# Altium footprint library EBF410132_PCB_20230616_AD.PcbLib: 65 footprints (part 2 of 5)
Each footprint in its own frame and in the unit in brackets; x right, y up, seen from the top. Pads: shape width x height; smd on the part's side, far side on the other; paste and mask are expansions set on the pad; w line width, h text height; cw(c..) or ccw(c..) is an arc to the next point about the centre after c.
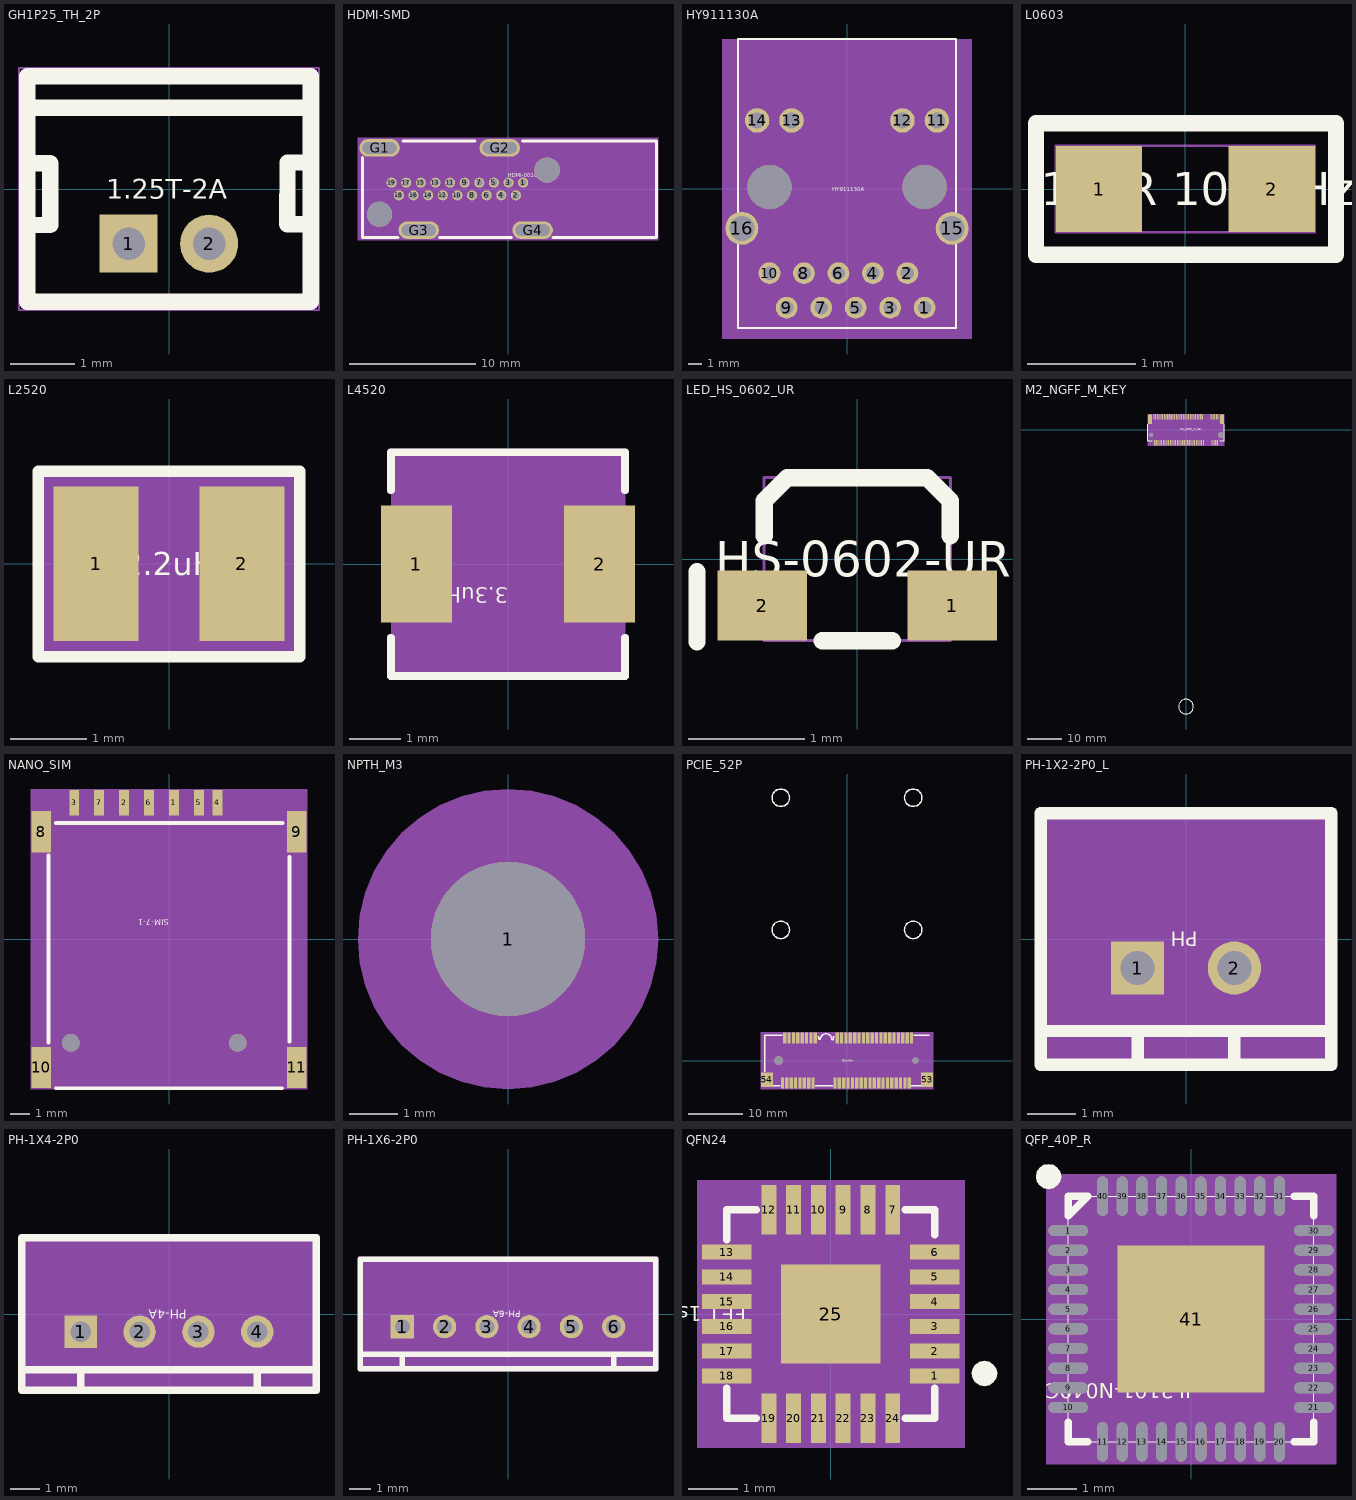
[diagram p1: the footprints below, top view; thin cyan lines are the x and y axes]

## GH1P25_TH_2P [mm] "GH1P25_TH_2P"
pads (2):
  rect 0.9x0.9 hole 0.5: 1(-0.626,-0.849)
  round 0.9 hole 0.5: 2(0.624,-0.849)
Top Overlay:
  lines w0.254: -2.202,0.401 -1.841,0.401 -1.841,-0.559 -2.161,-0.559 ; -2.201,1.262 2.199,1.262 ; 2.159,-0.549 1.839,-0.548 1.839,0.411 2.2,0.411 ; 2.199,-1.749 -2.201,-1.749 -2.201,1.751 2.199,1.751 ; 2.202,-1.751 2.202,1.749
  text "1.25T-2A" at -0.975,-0.152 h0.3
Top 3D Body:
  lines w0.025: -2.329,-1.878 2.329,-1.878 2.329,1.878 -2.329,1.878 -2.329,-1.878
Mechanical 15:
  text "2" at 0.37,-0.849 h0.64
  text "1" at -0.88,-0.849 h0.64

## HDMI-SMD [mm] "HDMI-SMD"
pads (25):
  round 0.8 hole 0.55: 1(1.194,0.5) 2(0.626,-0.5) 3(0.039,0.5) 4(-0.531,-0.5) 5(-1.116,0.5) 6(-1.687,-0.5) 7(-2.271,0.5) 8(-2.843,-0.5) 9(-3.425,0.5) 10(-3.998,-0.5) 11(-4.581,0.5) 12(-5.154,-0.5) 13(-5.736,0.5) 14(-6.31,-0.5) 15(-6.891,0.5) 16(-7.467,-0.5) 17(-8.045,0.5) 18(-8.623,-0.5) 19(-9.2,0.5)
  oval 3.2x1.4 hole 2.7 slot 0.9 at 90 deg: G1(-10.156,3.25) G2(-0.656,3.25) G3(-7.056,-3.25) G4(1.945,-3.25)
  round 2 hole 2 unplated: ""(-10.156,-2) ""(3.094,1.5)
Top Overlay:
  lines w0.254: -11.511,2.466 -11.511,-3.833 -8.699,-3.833 -8.696,-3.83 ; -8.295,3.786 -2.617,3.786 ; -5.422,-3.834 0.277,-3.834 ; 1.151,3.786 11.73,3.786 11.73,-3.834 3.588,-3.834 3.584,-3.83
  text "HDMI-001C" at 0,0.945 h0.3
Top 3D Body:
  region: -11.857,-4.052 11.857,-4.052 11.857,4.052 -11.857,4.052
Mechanical 15:
  text "2" at 0.626,-0.246 h0.64
  text "8" at -2.843,-0.246 h0.64
  text "5" at -1.116,0.754 h0.64
  text "11" at -4.581,1.008 h0.64
  text "17" at -8.045,1.008 h0.64
  text "13" at -5.736,1.008 h0.64
  text "18" at -8.623,0.008 h0.64
  text "19" at -9.2,1.008 h0.64
  text "G2" at -0.656,3.758 h0.64
  text "G4" at 1.945,-2.742 h0.64
  text "G1" at -10.156,3.758 h0.64
  text "G3" at -7.056,-2.742 h0.64
  text "15" at -6.891,1.008 h0.64
  text "16" at -7.467,0.008 h0.64
  text "12" at -5.154,0.008 h0.64
  text "10" at -3.998,0.008 h0.64
  text "9" at -3.425,0.754 h0.64
  text "7" at -2.271,0.754 h0.64
  text "6" at -1.687,-0.246 h0.64
  text "4" at -0.531,-0.246 h0.64
  text "3" at 0.039,0.754 h0.64
  text "1" at 1.194,0.754 h0.64
  text "14" at -6.31,0.008 h0.64
3D body: height 3.81, standoff 0, extent -11.857,-4.052 11.857,4.052

## HY911130A [mm] "HY911130A"
pads (18):
  round 1.6 hole 1: 1(5.72,-8.74) 2(4.45,-6.2) 3(3.18,-8.74) 4(1.91,-6.2) 5(0.64,-8.74) 6(-0.63,-6.2) 7(-1.9,-8.74) 8(-3.17,-6.2) 9(-4.44,-8.74) 10(-5.71,-6.2)
  round 1.8 hole 1.2: 11(6.625,5.05) 12(4.085,5.05) 13(-4.085,5.05) 14(-6.625,5.05)
  round 2.43 hole 1.83: 15(7.745,-2.9) 16(-7.745,-2.9)
  round 3.25 hole 3.25 unplated: ""(-5.715,0.15) ""(5.715,0.15)
Top Overlay:
  lines w0.15: -8.02,-10.25 -8.02,11.05 8.02,11.05 8.02,-10.25 -8.02,-10.25
  text "HY911130A" at -1.097,-0.152 h0.3
Top 3D Body:
  region: -9.2,11.05 -9.2,-11.05 9.2,-11.05 9.2,11.05
Mechanical 15:
  text "15" at 6.932,-2.9 h1.02
  text "16" at -8.558,-2.9 h1.02
  text "13" at -4.898,5.05 h1.02
  text "11" at 5.812,5.05 h1.02
  text "1" at 5.314,-8.74 h1.02
  text "9" at -4.846,-8.74 h1.02
  text "12" at 3.272,5.05 h1.02
  text "8" at -3.576,-6.2 h1.02
  text "6" at -1.036,-6.2 h1.02
  text "7" at -2.306,-8.74 h1.02
  text "4" at 1.504,-6.2 h1.02
  text "10" at -6.523,-6.2 h1.02
  text "3" at 2.774,-8.74 h1.02
  text "2" at 4.044,-6.2 h1.02
  text "14" at -7.438,5.05 h1.02
  text "5" at 0.234,-8.74 h1.02
3D body: height 3.81, standoff 0, extent -9.2,-11.05 9.2,11.05

## L0603 [mil] "L0603"
pads (2):
  rect 31.5x31.5 smd: 1(-31.5,0) 2(31.5,0)
Top Overlay:
  lines w6: -54.5,-24 55,-24 55,24 -54.5,24 -54.5,-24
  text "100R 100MHz" at -52.8,-6 h12
Top 3D Body:
  lines w1: -47.24,-15.75 47.24,-15.75 47.24,15.75 -47.24,15.75 -47.24,-15.75
Mechanical 15:
  text "1" at -49.5,0 h45
  text "2" at 13.5,0 h45

## L2520 [mil] "L2520"
pads (2):
  rect 44x80 smd: 1(-37.75,0) 2(37.75,0)
Top Overlay:
  lines w6: -67.68,-48.15 -67.68,47.92 67.67,47.92 67.67,-48.15 -67.67,-48.15 -67.68,-48.15
  text "2.2uH" at -24,-6 h12
Top 3D Body:
  region: -65,-45 65,-45 65,45 -65,45
Mechanical 15:
  text "2" at 33.03,0 h11.81
  text "1" at -42.47,0 h11.81
3D body: height 150, standoff 0, extent -65,-45 65,45

## L4520 [mm] "L4520"
pads (2):
  rect 1.4x2.3 smd: 1(-1.803,-0.002) 2(1.798,-0.002)
Top Overlay:
  lines w0.15: -2.302,-1.452 -2.302,-2.202 2.298,-2.202 2.298,-1.452 ; -2.302,1.448 -2.302,2.198 2.298,2.198 2.298,1.448
  text "3.3uH" at 0,-0.457 h0.3
Top 3D Body:
  region: -2.302,-2.202 2.303,-2.202 2.303,2.203 -2.302,2.203
Mechanical 15:
  text "1" at -1.803,-0.256 h0.64
  text "2" at 1.798,-0.256 h0.64
Top Assembly:
  lines w0.15: -2.302,-1.452 -2.302,-2.202 2.298,-2.202 2.298,-1.452 ; -2.302,1.448 -2.302,2.198 2.298,2.198 2.298,1.448
3D body: height 3.81, standoff 0, extent -2.302,-2.202 2.303,2.203

## LED_HS_0602_UR [mm] "LED_HS_0602_UR"
pads (2):
  rect 0.77x0.6 smd: 1(0.815,-0.4) 2(-0.815,-0.4)
Top Overlay:
  lines w0.15: -1.376,-0.71 -1.376,-0.11 ; -0.8,0.2 -0.8,0.5 -0.6,0.7 0.6,0.7 0.8,0.5 0.8,0.2 ; -0.3,-0.7 0.3,-0.7
  text "HS-0602-UR" at -1.219,-0.152 h0.3
Top 3D Body:
  lines w0.025: -0.8,-0.7 0.8,-0.7 0.8,0.7 -0.8,0.7 -0.8,-0.7
Mechanical 15:
  text "1" at 0.695,-0.4 h0.3
  text "2" at -0.935,-0.4 h0.3

## M2_NGFF_M_KEY [mm] "M2_NGFF_M_KEY"
pads (71):
  rect 0.3x1.55 smd: 1(-9.25,3.762) 2(-9,-3.687) 3(-8.75,3.762) 4(-8.5,-3.687) 5(-8.25,3.762) 6(-8,-3.687) 7(-7.75,3.762) 8(-7.5,-3.687) 9(-7.25,3.762) 10(-7,-3.687) 11(-6.75,3.762) 12(-6.5,-3.687) 13(-6.25,3.762) 14(-6,-3.687) 15(-5.75,3.762) 16(-5.5,-3.687) 17(-5.25,3.762) 18(-5,-3.687) 19(-4.75,3.762) 20(-4.5,-3.687) 21(-4.25,3.762) 22(-4,-3.687) 23(-3.75,3.762) 24(-3.5,-3.687) 25(-3.25,3.762) 26(-3,-3.687) 27(-2.75,3.762) 28(-2.5,-3.687) 29(-2.25,3.762) 30(-2,-3.687) 31(-1.75,3.762) 32(-1.5,-3.687) 33(-1.25,3.762) 34(-1,-3.687) 35(-0.75,3.762) 36(-0.5,-3.687) 37(-0.25,3.762) 38(0,-3.687) 39(0.25,3.762) 40(0.5,-3.687) 41(0.75,3.762) 42(1,-3.687) 43(1.25,3.762) 44(1.5,-3.687) 45(1.75,3.762) 46(2,-3.687) 47(2.25,3.762) 48(2.5,-3.687) 49(2.75,3.762) 50(3,-3.687) 51(3.25,3.762) 52(3.5,-3.687) 53(3.75,3.762) 54(4,-3.687) 55(4.25,3.762) 56(4.5,-3.687) 57(4.75,3.762) 58(5,-3.687) 67(7.25,3.762) 68(7.5,-3.687) 69(7.75,3.762) 70(8,-3.687) 71(8.25,3.762) 72(8.5,-3.687) 73(8.75,3.762) 74(9,-3.687) 75(9.25,3.762)
  rect 1.2x2.75 smd: 76(10.35,3.062) 77(-10.35,3.062)
  round 1.1 hole 1.1 unplated: ""(-10,-1.438)
  round 1.6 hole 1.6 unplated: ""(10,-1.438)
Top Overlay:
  circle w0.127: c0,-79.688 r2.11
  lines w0.127: -10.95,1.608 -10.95,-3.128 -9.749,-3.128 ; 9.779,-3.128 10.95,-3.128 10.95,1.608
  text "M2_NGFF_M_KEY" at -1.585,-0.152 h0.3
Top 3D Body:
  region: -10.95,-4.563 10.95,-4.563 10.95,4.563 -10.95,4.563
Mechanical 15:
  text "50" at 2.492,-3.687 h0.64
  text "54" at 3.492,-3.687 h0.64
  text "52" at 2.992,-3.687 h0.64
  text "29" at -2.758,3.762 h0.64
  text "31" at -2.258,3.762 h0.64
  text "41" at 0.242,3.762 h0.64
  text "43" at 0.742,3.762 h0.64
  text "12" at -7.008,-3.687 h0.64
  text "14" at -6.508,-3.687 h0.64
  text "16" at -6.008,-3.687 h0.64
  text "18" at -5.508,-3.687 h0.64
  text "4" at -8.754,-3.687 h0.64
  text "2" at -9.254,-3.687 h0.64
  text "70" at 7.392,-3.963 h0.64
  text "72" at 7.992,-3.963 h0.64
  text "74" at 8.592,-3.963 h0.64
  text "21" at -4.758,3.762 h0.64
  text "15" at -6.258,3.762 h0.64
  text "9" at -7.504,3.762 h0.64
  text "3" at -9.004,3.762 h0.64
  text "57" at 4.242,3.762 h0.64
  text "51" at 2.742,3.762 h0.64
  text "45" at 1.242,3.762 h0.64
  text "39" at -0.258,3.762 h0.64
  text "33" at -1.758,3.762 h0.64
  text "27" at -3.258,3.762 h0.64
  text "75" at 8.792,3.437 h0.64
  text "73" at 8.292,3.437 h0.64
  text "71" at 7.692,3.437 h0.64
  text "1" at -9.504,3.762 h0.64
  text "76" at 9.842,3.062 h0.64
  text "77" at -10.858,3.062 h0.64
  text "38" at -0.508,-3.687 h0.64
  text "55" at 3.742,3.762 h0.64
  text "47" at 1.742,3.762 h0.64
  text "49" at 2.242,3.762 h0.64
  text "10" at -7.508,-3.687 h0.64
  text "53" at 3.242,3.762 h0.64
  text "35" at -1.258,3.762 h0.64
  text "37" at -0.758,3.762 h0.64
  text "68" at 6.792,-3.963 h0.64
  text "13" at -6.758,3.762 h0.64
  text "25" at -3.758,3.762 h0.64
  text "11" at -7.258,3.762 h0.64
  text "23" at -4.258,3.762 h0.64
  text "7" at -8.004,3.762 h0.64
  text "19" at -5.258,3.762 h0.64
  text "5" at -8.504,3.762 h0.64
  text "17" at -5.758,3.762 h0.64
  text "32" at -2.008,-3.687 h0.64
  text "30" at -2.508,-3.687 h0.64
  text "28" at -3.008,-3.687 h0.64
  text "26" at -3.508,-3.687 h0.64
  text "24" at -4.008,-3.687 h0.64
  text "22" at -4.508,-3.687 h0.64
  text "20" at -5.008,-3.687 h0.64
  text "8" at -7.754,-3.687 h0.64
  text "67" at 6.392,3.437 h0.64
  text "48" at 1.992,-3.687 h0.64
  text "46" at 1.492,-3.687 h0.64
  text "44" at 0.992,-3.687 h0.64
  text "42" at 0.492,-3.687 h0.64
  text "40" at -0.008,-3.687 h0.64
  text "36" at -1.008,-3.687 h0.64
  text "34" at -1.508,-3.687 h0.64
  text "6" at -8.254,-3.687 h0.64
  text "58" at 4.492,-3.687 h0.64
  text "56" at 3.992,-3.687 h0.64
  text "69" at 7.292,3.437 h0.64
3D body: height 3.81, standoff 0, extent -10.95,-4.563 10.95,4.563

## NANO_SIM [mm] "NANO_SIM"
pads (13):
  rect 0.5x1.3 smd: 1(0.25,6.94) 2(-2.29,6.94) 3(-4.83,6.94) 4(2.47,6.94) 5(1.52,6.94) 6(-1.02,6.94) 7(-3.56,6.94)
  rect 1x2.1 smd: 8(-6.5,5.46) 9(6.5,5.46) 10(-6.5,-6.54) 11(6.5,-6.54)
  round 0.9 hole 0.9 unplated: ""(-5,-5.29) ""(3.5,-5.29)
Top Overlay:
  lines w0.2: -6.145,-5.268 -6.145,4.247 ; -5.756,5.9 5.784,5.9 ; -5.749,-7.6 0,-7.6 5.749,-7.6 ; 6.145,-5.215 6.145,4.189
  text "SIM-7-1" at 0,1.006 h0.3
Top 3D Body:
  region: -7.05,-7.64 -7.05,7.64 7.05,7.64 7.05,-7.64
Mechanical 15:
  text "5" at 1.52,7.062 h0.3
  text "10" at -6.5,-6.296 h0.3
  text "8" at -6.5,5.582 h0.3
  text "9" at 6.5,5.582 h0.3
  text "11" at 6.5,-6.296 h0.3
  text "3" at -4.83,7.062 h0.3
  text "1" at 0.25,7.062 h0.3
  text "2" at -2.29,7.062 h0.3
  text "7" at -3.56,7.062 h0.3
  text "6" at -1.02,7.062 h0.3
  text "4" at 2.47,7.062 h0.3
3D body: height 3.81, standoff 0, extent -7.05,-7.64 7.05,7.64

## NPTH_M3 [mm] "NPTH_M3"
pads (1):
  round 3.2 hole 3.2 unplated: 1(0,0)
Top Overlay:
  text "NPTH_M3" at -0.853,-0.152 h0.3
Top 3D Body:
  region: 3.11,0 3.071,0.486 2.957,0.961 2.771,1.412 2.516,1.828 2.199,2.199 1.828,2.516 1.412,2.771 0.961,2.957 0.486,3.071 0,3.11 -0.486,3.071 -0.961,2.957 -1.412,2.771 -1.551,2.686 -1.828,2.516 -2.199,2.199 -2.516,1.828 -2.771,1.412 -2.957,0.961 -3.071,0.486 -3.11,0 -3.071,-0.486 -2.957,-0.961 -2.771,-1.412 -2.516,-1.828 -2.199,-2.199 -1.828,-2.516 -1.551,-2.686 -1.412,-2.771 -0.961,-2.957 -0.486,-3.071 0,-3.11 0.486,-3.071 0.961,-2.957 1.412,-2.771 1.828,-2.516 2.199,-2.199 2.516,-1.828 2.771,-1.412 2.957,-0.961 3.071,-0.486
Mechanical 15:
  text "1" at -0.254,0 h0.64
Top Assembly:
  dashed: 3.11,0 3.071,0.486 2.957,0.961 2.771,1.412 2.516,1.828 2.199,2.199 1.828,2.516 1.412,2.771 0.961,2.957 0.486,3.071 0,3.11 -0.486,3.071 -0.961,2.957 -1.412,2.771 -1.551,2.686 -1.828,2.516 -2.199,2.199 -2.516,1.828 -2.771,1.412 -2.957,0.961 -3.071,0.486 -3.11,0 -3.071,-0.486 -2.957,-0.961 -2.771,-1.412 -2.516,-1.828 -2.199,-2.199 -1.828,-2.516 -1.551,-2.686 -1.412,-2.771 -0.961,-2.957 -0.486,-3.071 0,-3.11 0.486,-3.071 0.961,-2.957 1.412,-2.771 1.828,-2.516 2.199,-2.199 2.516,-1.828 2.771,-1.412 2.957,-0.961 3.071,-0.486
3D body: height 3.81, standoff 0, extent -3.11,-3.11 3.11,3.11

## PCIE_52P [mm] "PCIE_52P"
pads (56):
  rect 0.6x2 smd: 1(-11.8,-4.1) 2(-11.4,4.1) 3(-11,-4.1) 4(-10.6,4.1) 5(-10.2,-4.1) 6(-9.8,4.1) 7(-9.4,-4.1) 8(-9,4.1) 9(-8.6,-4.1) 10(-8.2,4.1) 11(-7.8,-4.1) 12(-7.4,4.1) 13(-7,-4.1) 14(-6.6,4.1) 15(-6.2,-4.1) 16(-5.8,4.1) 17(-2.2,-4.1) 18(-1.8,4.1) 19(-1.4,-4.1) 20(-1,4.1) 21(-0.6,-4.1) 22(-0.2,4.1) 23(0.2,-4.1) 24(0.6,4.1) 25(1,-4.1) 26(1.4,4.1) 27(1.8,-4.1) 28(2.2,4.1) 29(2.6,-4.1) 30(3,4.1) 31(3.4,-4.1) 32(3.8,4.1) 33(4.2,-4.1) 34(4.6,4.1) 35(5,-4.1) 36(5.4,4.1) 37(5.8,-4.1) 38(6.2,4.1) 39(6.6,-4.1) 40(7,4.1) 41(7.4,-4.1) 42(7.8,4.1) 43(8.2,-4.1) 44(8.6,4.1) 45(9,-4.1) 46(9.4,4.1) 47(9.8,-4.1) 48(10.2,4.1) 49(10.6,-4.1) 50(11,4.1) 51(11.4,-4.1) 52(11.8,4.1)
  rect 2.15x2.6 smd: 53(14.65,-3.5) 54(-14.65,-3.5)
  round 1.6 hole 1.6 unplated: ""(-12.5,0)
  round 1.1 hole 1.1 unplated: ""(12.5,0)
Top Overlay:
  circle w0.25: c12.1,48.049 r1.6
  circle w0.25: c-12.1,48.049 r1.6
  circle w0.25: c-12.1,23.899 r1.6
  circle w0.25: c12.1,23.899 r1.6
  lines w0.25: -15,-2.011 -15,4.6 -11.869,4.6 ; -13.487,-4.6 -12.194,-4.6 ; -5.803,-4.6 -2.572,-4.6 ; -5.325,4.387 -5.165,4.387 -5.165,3.883 -4.887,3.883 cw(c-3.843,3.859) -2.8,3.859 -2.8,3.847 -2.474,3.847 -2.474,4.381 -2.29,4.381 ; 11.787,-4.6 13.477,-4.6 ; 12.237,4.6 15,4.6
  text "MINI-PCIE" at 1.097,0.152 h0.3
Top 3D Body:
  region: -15.8,-5.2 -15.8,5.2 15.8,5.2 15.8,-5.2
Mechanical 15:
  text "11" at -7.312,-4.1 h0.3
  text "13" at -6.512,-4.1 h0.3
  text "20" at -0.512,4.1 h0.3
  text "33" at 4.688,-4.1 h0.3
  text "23" at 0.688,-4.1 h0.3
  text "38" at 6.688,4.1 h0.3
  text "22" at 0.288,4.1 h0.3
  text "25" at 1.488,-4.1 h0.3
  text "1" at -11.556,-4.1 h0.3
  text "36" at 5.888,4.1 h0.3
  text "31" at 3.888,-4.1 h0.3
  text "7" at -9.156,-4.1 h0.3
  text "26" at 1.888,4.1 h0.3
  text "34" at 5.088,4.1 h0.3
  text "50" at 11.488,4.1 h0.3
  text "53" at 15.138,-3.5 h0.3
  text "40" at 7.488,4.1 h0.3
  text "9" at -8.356,-4.1 h0.3
  text "15" at -5.712,-4.1 h0.3
  text "4" at -10.356,4.1 h0.3
  text "37" at 6.288,-4.1 h0.3
  text "35" at 5.488,-4.1 h0.3
  text "29" at 3.088,-4.1 h0.3
  text "27" at 2.288,-4.1 h0.3
  text "21" at -0.112,-4.1 h0.3
  text "43" at 8.688,-4.1 h0.3
  text "18" at -1.312,4.1 h0.3
  text "54" at -14.162,-3.5 h0.3
  text "8" at -8.756,4.1 h0.3
  text "14" at -6.112,4.1 h0.3
  text "10" at -7.712,4.1 h0.3
  text "12" at -6.912,4.1 h0.3
  text "24" at 1.088,4.1 h0.3
  text "2" at -11.156,4.1 h0.3
  text "52" at 12.288,4.1 h0.3
  text "39" at 7.088,-4.1 h0.3
  text "41" at 7.888,-4.1 h0.3
  text "32" at 4.288,4.1 h0.3
  text "19" at -0.912,-4.1 h0.3
  text "44" at 9.088,4.1 h0.3
  text "46" at 9.888,4.1 h0.3
  text "30" at 3.488,4.1 h0.3
  text "28" at 2.688,4.1 h0.3
  text "5" at -9.956,-4.1 h0.3
  text "16" at -5.312,4.1 h0.3
  text "17" at -1.712,-4.1 h0.3
  text "51" at 11.888,-4.1 h0.3
  text "49" at 11.088,-4.1 h0.3
  text "47" at 10.288,-4.1 h0.3
  text "45" at 9.488,-4.1 h0.3
  text "48" at 10.688,4.1 h0.3
  text "6" at -9.556,4.1 h0.3
  text "3" at -10.756,-4.1 h0.3
  text "42" at 8.288,4.1 h0.3
Top Assembly:
  dashed: -15.8,5.2 -15.8,-5.2 15.8,-5.2 15.8,5.2
3D body: height 3.81, standoff 0, extent -15.8,-5.2 15.8,5.2

## PH-1X2-2P0_L [mm] "PH-1X2-2P0_L"
pads (2):
  rect 1.1x1.1 hole 0.7: 1(-1,-0.6)
  round 1.1 hole 0.7: 2(1,-0.6)
Top Overlay:
  lines w0.254: -3,-1.9 3,-1.9 ; -1,-2.6 -1,-1.9 ; 1,-2.6 1,-1.9 ; -3,-2.6 -3,2.6 3,2.6 3,-2.6 -3,-2.6
  text "PH" at 0.244,0.152 h0.3
Top 3D Body:
  region: -3.1,2.7 -3.1,-2.7 3.1,-2.7 3.1,2.7
Mechanical 15:
  text "2" at 1.254,-0.6 h0.64
  text "1" at -0.746,-0.6 h0.64
Top Assembly:
  dashed: -3.1,2.7 -3.1,-2.7 3.1,-2.7 3.1,2.7
3D body: height 3.81, standoff 0, extent -3.1,-2.7 3.1,2.7

## PH-1X4-2P0 [mm] "PH-1X4-2P0"
pads (4):
  rect 1.1x1.1 hole 0.7: 1(-3,-0.6)
  round 1.1 hole 0.7: 2(-1,-0.6) 3(1,-0.6) 4(3,-0.6)
Top Overlay:
  lines w0.254: -5,-1.9 5,-1.9 ; -3,-2.6 -3,-1.9 ; 3,-2.6 3,-1.9 ; -5,-2.6 -5,2.6 5,2.6 5,-2.6 -5,-2.6
  text "PH-4A" at 0.61,0.152 h0.3
Top 3D Body:
  region: -5.1,2.7 -5.1,-2.7 5.1,-2.7 5.1,2.7
Mechanical 15:
  text "4" at 3.376,-0.6 h0.94
  text "2" at -0.624,-0.6 h0.94
  text "3" at 1.376,-0.6 h0.94
  text "1" at -2.624,-0.6 h0.94
3D body: height 3.81, standoff 0, extent -5.1,-2.7 5.1,2.7

## PH-1X6-2P0 [mm] "PH-1X6-2P0"
pads (6):
  rect 1.1x1.1 hole 0.7: 1(-5,-0.6)
  round 1.1 hole 0.7: 2(-3,-0.6) 3(-1,-0.6) 4(1,-0.6) 5(3,-0.6) 6(5,-0.6)
Top Overlay:
  lines w0.254: -7,-1.9 7,-1.9 ; -5,-2.6 -5,-1.9 ; 5,-2.6 5,-1.9 ; -7,-2.6 7,-2.6 7,2.6 -7,2.6 -7,-2.6
  text "PH-6A" at 0.61,0.152 h0.3
Top 3D Body:
  region: -7.1,2.7 -7.1,-2.7 7.1,-2.7 7.1,2.7
Mechanical 15:
  text "1" at -4.746,-0.6 h0.64
  text "5" at 3.254,-0.6 h0.64
  text "2" at -2.746,-0.6 h0.64
  text "4" at 1.254,-0.6 h0.64
  text "6" at 5.254,-0.6 h0.64
  text "3" at -0.746,-0.6 h0.64
Top Assembly:
  dashed: -7.1,2.7 -7.1,-2.7 7.1,-2.7 7.1,2.7
3D body: height 3.81, standoff 0, extent -7.1,-2.7 7.1,2.7

## QFN24 [mm] "QFN24"
pads (25):
  rect 1x0.3 smd: 1(2.1,-1.25) 2(2.1,-0.75) 3(2.1,-0.25) 4(2.1,0.25) 5(2.1,0.75) 6(2.1,1.25) 13(-2.1,1.25) 14(-2.1,0.75) 15(-2.1,0.25) 16(-2.1,-0.25) 17(-2.1,-0.75) 18(-2.1,-1.25)
  rect 0.3x1 smd: 7(1.25,2.1) 8(0.75,2.1) 9(0.25,2.1) 10(-0.25,2.1) 11(-0.75,2.1) 12(-1.25,2.1) 19(-1.25,-2.1) 20(-0.75,-2.1) 21(-0.25,-2.1) 22(0.25,-2.1) 23(0.75,-2.1) 24(1.25,-2.1)
  rect 2x2 smd: 25(0,0)
Top Overlay:
  dashed: 3.355,-1.2 3.335,-1.298 3.28,-1.38 3.198,-1.435 3.1,-1.455 3.002,-1.435 2.975,-1.417 2.92,-1.38 2.865,-1.298 2.845,-1.2 2.865,-1.102 2.92,-1.02 2.975,-0.983 3.002,-0.965 3.1,-0.945 3.198,-0.965 3.28,-1.02 3.335,-1.102
  lines w0.15: -2.1,-1.5 -2.1,-2.1 -1.5,-2.1 ; -2.1,1.5 -2.1,2.1 -1.5,2.1 ; 1.5,-2.1 2.1,-2.1 2.1,-1.5 ; 1.5,2.1 2.1,2.1 2.1,1.6
  text "FE1.1s-BQFN24B" at -1.707,0.152 h0.3
Top 3D Body:
  region: 2.7,2.7 -2.7,2.7 -2.7,-2.7 2.7,-2.7
Mechanical 15:
  text "19" at -1.555,-2.1 h0.38
  text "15" at -2.405,0.25 h0.38
  text "14" at -2.405,0.75 h0.38
  text "25" at -0.305,0 h0.38
  text "7" at 1.098,2.1 h0.38
  text "8" at 0.598,2.1 h0.38
  text "9" at 0.098,2.1 h0.38
  text "10" at -0.555,2.1 h0.38
  text "11" at -1.055,2.1 h0.38
  text "12" at -1.555,2.1 h0.38
  text "4" at 1.948,0.25 h0.38
  text "3" at 1.948,-0.25 h0.38
  text "1" at 1.948,-1.25 h0.38
  text "21" at -0.555,-2.1 h0.38
  text "20" at -1.055,-2.1 h0.38
  text "17" at -2.405,-0.75 h0.38
  text "18" at -2.405,-1.25 h0.38
  text "16" at -2.405,-0.25 h0.38
  text "13" at -2.405,1.25 h0.38
  text "2" at 1.948,-0.75 h0.38
  text "24" at 0.945,-2.1 h0.38
  text "23" at 0.445,-2.1 h0.38
  text "22" at -0.055,-2.1 h0.38
  text "6" at 1.948,1.25 h0.38
  text "5" at 1.948,0.75 h0.38
Top Assembly:
  lines w0.2: -2.05,-2.05 2.05,-2.05 2.05,2.05 -2.05,2.05 -2.05,-2.05
3D body: height 3.81, standoff 0, extent -2.7,-2.7 2.7,2.7

## QFP_40P_R [mil] "QFP_40P_R"
pads (41):
  oval 31.5x8.66 smd: 1(-98.43,70.87) 2(-98.43,55.12) 3(-98.43,39.37) 4(-98.43,23.62) 5(-98.43,7.87) 6(-98.43,-7.87) 7(-98.43,-23.62) 8(-98.43,-39.37) 9(-98.43,-55.12) 10(-98.43,-70.87) 21(98.43,-70.87) 22(98.43,-55.12) 23(98.43,-39.37) 24(98.43,-23.62) 25(98.43,-7.87) 26(98.43,7.87) 27(98.43,23.62) 28(98.43,39.37) 29(98.43,55.12) 30(98.43,70.87)
  oval 8.66x31.5 smd: 11(-70.87,-98.43) 12(-55.12,-98.43) 13(-39.37,-98.43) 14(-23.62,-98.43) 15(-7.87,-98.43) 16(7.87,-98.43) 17(23.62,-98.43) 18(39.37,-98.43) 19(55.12,-98.43) 20(70.87,-98.43) 31(70.87,98.43) 32(55.12,98.43) 33(39.37,98.43) 34(23.62,98.43) 35(7.87,98.43) 36(-7.87,98.43) 37(-23.62,98.43) 38(-39.37,98.43) 39(-55.12,98.43) 40(-70.87,98.43)
  rect 118.11x118.11 smd: 41(0,0)
Top Overlay:
  dashed: -114.17,124.21 -118.01,123.44 -121.27,121.27 -123.44,118.01 -124.21,114.17 -123.44,110.33 -122.71,109.24 -121.27,107.08 -118.01,104.9 -114.17,104.14 -110.33,104.9 -107.08,107.08 -105.63,109.24 -104.9,110.33 -104.14,114.17 -104.9,118.01 -107.08,121.27 -110.33,123.44
  lines w1: -98.43,-98.43 98.43,-98.43 98.43,98.43 -98.43,98.43 -98.43,-98.43
  lines w5.91: -98.43,-82.68 -98.43,-98.43 -82.68,-98.43 ; 82.68,-98.43 98.43,-98.43 98.43,-82.68 ; 82.68,98.43 98.43,98.43 98.43,82.68 ; -98.43,82.68 -98.43,98.43 -82.68,98.43 -98.43,82.68
  text "JL2101-N040C" at 0.01,-51.6 h12
Mechanical 5:
  dashed: -116.14,-116.14 116.14,-116.14 116.14,116.14 -116.14,116.14
Top 3D Body:
  region: -116.14,-116.14 116.14,-116.14 116.14,116.14 -116.14,116.14
Mechanical 15:
  text "12" at -55.12,-114.43 h20
  text "35" at 7.87,82.43 h20
  text "32" at 55.12,82.43 h20
  text "37" at -23.62,82.43 h20
  text "36" at -7.87,82.43 h20
  text "10" at -98.43,-86.87 h20
  text "34" at 23.62,82.43 h20
  text "9" at -98.43,-63.12 h20
  text "7" at -98.43,-31.62 h20
  text "5" at -98.43,-0.13 h20
  text "4" at -98.43,15.62 h20
  text "41" at 0,-16 h20
  text "2" at -98.43,47.12 h20
  text "1" at -98.43,62.87 h20
  text "28" at 98.43,23.37 h20
  text "11" at -70.87,-114.43 h20
  text "40" at -70.87,82.43 h20
  text "29" at 98.43,39.12 h20
  text "31" at 70.87,82.43 h20
  text "8" at -98.43,-47.37 h20
  text "38" at -39.37,82.43 h20
  text "3" at -98.43,31.37 h20
  text "21" at 98.43,-86.87 h20
  text "14" at -23.62,-114.43 h20
  text "13" at -39.37,-114.43 h20
  text "20" at 70.87,-114.43 h20
  text "19" at 55.12,-114.43 h20
  text "15" at -7.87,-114.43 h20
  text "16" at 7.87,-114.43 h20
  text "17" at 23.62,-114.43 h20
  text "18" at 39.37,-114.43 h20
  text "26" at 98.43,-8.13 h20
  text "27" at 98.43,7.62 h20
  text "22" at 98.43,-71.12 h20
  text "23" at 98.43,-55.37 h20
  text "24" at 98.43,-39.62 h20
  text "25" at 98.43,-23.87 h20
  text "33" at 39.37,82.43 h20
  text "39" at -55.12,82.43 h20
  text "30" at 98.43,54.87 h20
  text "6" at -98.43,-15.87 h20
Top Assembly:
  lines w1: -98.43,90.55 -90.55,98.43 ; -98.43,-98.43 98.43,-98.43 98.43,98.43 -98.43,98.43 -98.43,-98.43
3D body: height 150, standoff 0, extent -116.14,-116.14 116.14,116.14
